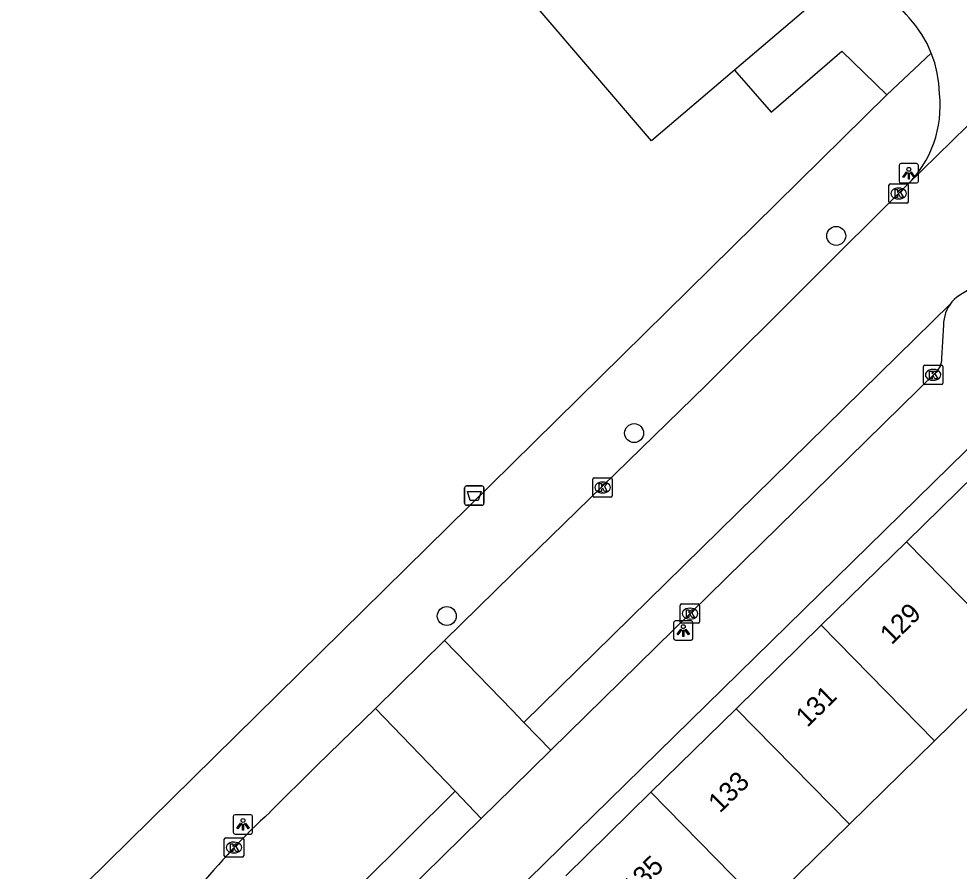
# Model space of a CAD drawing. Extents: x 159222 to 160346, y 381249 to 382166.
# Drawn here: x 159474.57 to 159523.05, y 381384.14 to 381428.08 of the extents above; entities that cross this region are included whole.
import ezdxf

# ---------------------------------------------------------------- set-up
doc = ezdxf.new("R2010")
doc.units = 0
for name, color, linetype in [('IMGEO_Afvalbak', 7, 'Continuous'), ('IMGEO_Boom', 7, 'Continuous'), ('IMGEO_Kolk', 7, 'Continuous'), ('IMGEO_Lichtpunt', 7, 'Continuous'), ('IMGEO_Pand', 7, 'Continuous'), ('IMGEO_Pand_nummerreeks', 7, 'Continuous'), ('IMGEO_Rijbaan_lokaal_gesloten', 7, 'Continuous'), ('IMGEO_Rijbaan_lokaal_open', 7, 'Continuous'), ('IMGEO_Voetpad_open', 7, 'Continuous')]:
    doc.layers.add(name, color=color, linetype=linetype)

msp = doc.modelspace()

# ---------------------------------------------------------------- linework, layer by layer
at = {"layer": 'IMGEO_Afvalbak'}
for p, q in [((159497.553, 381403.099), (159497.553, 381403.899)), ((159497.553, 381403.899), (159497.553, 381403.099)), ((159497.653, 381403.999), (159498.443, 381403.999)), ((159498.443, 381403.999), (159497.653, 381403.999)), ((159498.543, 381403.899), (159498.543, 381403.099)), ((159498.543, 381403.099), (159498.543, 381403.899)), ((159498.443, 381402.999), (159497.653, 381402.999)), ((159497.653, 381402.999), (159498.443, 381402.999))]:
    msp.add_line(p, q, dxfattribs=at)
msp.add_lwpolyline([(159497.696, 381403.713), (159498.4, 381403.713), (159498.251, 381403.243), (159497.845, 381403.243), (159497.696, 381403.713)], dxfattribs=at)
for centre, start, end in [((159497.653, 381403.899), 90, 180), ((159497.653, 381403.899), 90, 180), ((159498.443, 381403.899), 0, 90), ((159498.443, 381403.899), 360, 90), ((159497.653, 381403.099), 180, 270), ((159497.653, 381403.099), 180, 270), ((159498.443, 381403.099), 270, 0), ((159498.443, 381403.099), 270, 0)]:
    msp.add_arc(centre, 0.1, start, end, dxfattribs=at)
at = {"layer": 'IMGEO_Boom'}
for centre in [(159516.709, 381416.884), (159506.289, 381406.719), (159496.631, 381397.289)]:
    msp.add_circle(centre, 0.489, dxfattribs=at)
at = {"layer": 'IMGEO_Kolk'}
for p, q in [((159519.424, 381418.643), (159519.424, 381419.495)), ((159519.499, 381419.569), (159520.351, 381419.569)), ((159519.912, 381419.349), (159519.937, 381419.349)), ((159520.425, 381419.495), (159520.425, 381418.643)), ((159519.935, 381418.789), (159519.91, 381418.789)), ((159520.351, 381418.569), (159519.499, 381418.569)), ((159521.203, 381409.294), (159521.203, 381410.146)), ((159521.278, 381410.22), (159522.13, 381410.22)), ((159521.691, 381410), (159521.716, 381410)), ((159522.204, 381410.146), (159522.204, 381409.294)), ((159522.13, 381409.22), (159521.278, 381409.22)), ((159521.714, 381409.44), (159521.689, 381409.44)), ((159504.163, 381403.488), (159504.163, 381404.34)), ((159504.238, 381404.414), (159505.09, 381404.414)), ((159504.651, 381404.194), (159504.676, 381404.194)), ((159505.164, 381404.34), (159505.164, 381403.488)), ((159505.09, 381403.414), (159504.238, 381403.414)), ((159504.674, 381403.634), (159504.649, 381403.634)), ((159508.74, 381397.913), (159509.592, 381397.913)), ((159508.665, 381396.987), (159508.665, 381397.839)), ((159509.153, 381397.693), (159509.178, 381397.693)), ((159509.666, 381397.839), (159509.666, 381396.987)), ((159509.592, 381396.913), (159508.74, 381396.913)), ((159509.176, 381397.133), (159509.151, 381397.133)), ((159485.16, 381384.927), (159485.16, 381385.779)), ((159485.235, 381385.853), (159486.087, 381385.853)), ((159486.161, 381385.779), (159486.161, 381384.927)), ((159485.648, 381385.633), (159485.673, 381385.633)), ((159486.087, 381384.853), (159485.235, 381384.853)), ((159485.671, 381385.073), (159485.646, 381385.073))]:
    msp.add_line(p, q, dxfattribs=at)
for points in [[(159519.424, 381418.643), (159519.424, 381419.495)], [(159519.499, 381419.569), (159520.351, 381419.569)], [(159519.745, 381419.269), (159519.868, 381419.269), (159519.868, 381419.118), (159519.998, 381419.269), (159520.162, 381419.269), (159520.016, 381419.118), (159520.169, 381418.869), (159520.017, 381418.869), (159519.932, 381419.033), (159519.868, 381418.966), (159519.868, 381418.869), (159519.745, 381418.869), (159519.745, 381419.269)], [(159520.425, 381419.495), (159520.425, 381418.643)], [(159520.351, 381418.569), (159519.499, 381418.569)], [(159521.203, 381409.294), (159521.203, 381410.146)], [(159521.278, 381410.22), (159522.13, 381410.22)], [(159522.204, 381410.146), (159522.204, 381409.294)], [(159521.524, 381409.92), (159521.647, 381409.92), (159521.647, 381409.769), (159521.777, 381409.92), (159521.941, 381409.92), (159521.795, 381409.769), (159521.948, 381409.52), (159521.796, 381409.52), (159521.711, 381409.684), (159521.647, 381409.617), (159521.647, 381409.52), (159521.524, 381409.52), (159521.524, 381409.92)], [(159522.13, 381409.22), (159521.278, 381409.22)], [(159504.163, 381403.488), (159504.163, 381404.34)], [(159504.238, 381404.414), (159505.09, 381404.414)], [(159505.164, 381404.34), (159505.164, 381403.488)], [(159504.484, 381404.114), (159504.607, 381404.114), (159504.607, 381403.963), (159504.737, 381404.114), (159504.901, 381404.114), (159504.755, 381403.963), (159504.908, 381403.714), (159504.756, 381403.714), (159504.671, 381403.878), (159504.607, 381403.811), (159504.607, 381403.714), (159504.484, 381403.714), (159504.484, 381404.114)], [(159505.09, 381403.414), (159504.238, 381403.414)], [(159508.74, 381397.913), (159509.592, 381397.913)], [(159508.665, 381396.987), (159508.665, 381397.839)], [(159508.986, 381397.613), (159509.109, 381397.613), (159509.109, 381397.462), (159509.239, 381397.613), (159509.403, 381397.613), (159509.257, 381397.462), (159509.41, 381397.213), (159509.258, 381397.213), (159509.173, 381397.377), (159509.109, 381397.31), (159509.109, 381397.213), (159508.986, 381397.213), (159508.986, 381397.613)], [(159509.666, 381397.839), (159509.666, 381396.987)], [(159509.592, 381396.913), (159508.74, 381396.913)], [(159485.16, 381384.927), (159485.16, 381385.779)], [(159485.235, 381385.853), (159486.087, 381385.853)], [(159486.161, 381385.779), (159486.161, 381384.927)], [(159485.481, 381385.553), (159485.604, 381385.553), (159485.604, 381385.402), (159485.734, 381385.553), (159485.898, 381385.553), (159485.752, 381385.402), (159485.905, 381385.153), (159485.753, 381385.153), (159485.668, 381385.317), (159485.604, 381385.25), (159485.604, 381385.153), (159485.481, 381385.153), (159485.481, 381385.553)], [(159486.087, 381384.853), (159485.235, 381384.853)]]:
    msp.add_lwpolyline(points, dxfattribs=at)
for centre, start, end in [((159519.501, 381419.493), 91.552, 178.448), ((159519.501, 381419.493), 91.552, 178.448), ((159520.349, 381419.493), 1.552, 88.448), ((159520.349, 381419.493), 1.552, 88.448), ((159519.501, 381418.645), 181.552, 268.448), ((159519.501, 381418.645), 181.552, 268.448), ((159520.349, 381418.645), 271.552, 358.448), ((159520.349, 381418.645), 271.552, 358.448), ((159521.28, 381410.144), 91.552, 178.448), ((159521.28, 381410.144), 91.552, 178.448), ((159522.128, 381410.144), 1.552, 88.448), ((159522.128, 381410.144), 1.552, 88.448), ((159521.28, 381409.296), 181.552, 268.448), ((159521.28, 381409.296), 181.552, 268.448), ((159522.128, 381409.296), 271.552, 358.448), ((159522.128, 381409.296), 271.552, 358.448), ((159504.24, 381404.338), 91.552, 178.448), ((159504.24, 381404.338), 91.552, 178.448), ((159505.088, 381404.338), 1.552, 88.448), ((159505.088, 381404.338), 1.552, 88.448), ((159504.24, 381403.49), 181.552, 268.448), ((159504.24, 381403.49), 181.552, 268.448), ((159505.088, 381403.49), 271.552, 358.448), ((159505.088, 381403.49), 271.552, 358.448), ((159508.742, 381397.837), 91.552, 178.448), ((159508.742, 381397.837), 91.552, 178.448), ((159509.59, 381397.837), 1.552, 88.448), ((159509.59, 381397.837), 1.552, 88.448), ((159508.742, 381396.989), 181.552, 268.448), ((159508.742, 381396.989), 181.552, 268.448), ((159509.59, 381396.989), 271.552, 358.448), ((159509.59, 381396.989), 271.552, 358.448), ((159485.237, 381385.777), 91.552, 178.448), ((159485.237, 381385.777), 91.552, 178.448), ((159486.085, 381385.777), 1.552, 88.448), ((159486.085, 381385.777), 1.552, 88.448), ((159485.237, 381384.929), 181.552, 268.448), ((159485.237, 381384.929), 181.552, 268.448), ((159486.085, 381384.929), 271.552, 358.448), ((159486.085, 381384.929), 271.552, 358.448)]:
    msp.add_arc(centre, 0.0765, start, end, dxfattribs=at)
for centre, major_axis, ratio, start_param, end_param in [((159519.911, 381419.069), (-0.387, 0.002), 0.722429, 4.712389, 7.853982), ((159519.936, 381419.069), (-0.39, 0.002), 0.717154, 1.570796, 4.712389), ((159521.69, 381409.72), (-0.387, 0.002), 0.722429, 4.712389, 7.853982), ((159521.715, 381409.72), (-0.39, 0.002), 0.717154, 1.570796, 4.712389), ((159504.65, 381403.914), (-0.387, 0.002), 0.722429, 4.712389, 7.853982), ((159504.675, 381403.914), (-0.39, 0.002), 0.717154, 1.570796, 4.712389), ((159509.152, 381397.413), (-0.387, 0.002), 0.722429, 4.712389, 7.853982), ((159509.177, 381397.413), (-0.39, 0.002), 0.717154, 1.570796, 4.712389), ((159485.647, 381385.353), (-0.387, 0.002), 0.722429, 4.712389, 7.853982), ((159485.672, 381385.353), (-0.39, 0.002), 0.717154, 1.570796, 4.712389)]:
    msp.add_ellipse(centre, major_axis=major_axis, ratio=ratio, start_param=start_param, end_param=end_param, dxfattribs=at)
at = {"layer": 'IMGEO_Lichtpunt'}
for p, q in [((159519.951, 381420.517), (159519.951, 381419.71)), ((159519.951, 381420.517), (159519.951, 381419.71)), ((159520.853, 381420.612), (159520.045, 381420.612)), ((159520.853, 381420.612), (159520.045, 381420.612)), ((159520.947, 381419.71), (159520.947, 381420.517)), ((159520.947, 381419.71), (159520.947, 381420.517)), ((159520.045, 381419.616), (159520.853, 381419.616)), ((159520.045, 381419.616), (159520.853, 381419.616)), ((159508.325, 381396.945), (159508.325, 381396.138)), ((159508.325, 381396.945), (159508.325, 381396.138)), ((159509.227, 381397.04), (159508.419, 381397.04)), ((159509.227, 381397.04), (159508.419, 381397.04)), ((159509.321, 381396.138), (159509.321, 381396.945)), ((159509.321, 381396.138), (159509.321, 381396.945)), ((159508.419, 381396.044), (159509.227, 381396.044)), ((159508.419, 381396.044), (159509.227, 381396.044)), ((159485.628, 381386.95), (159485.628, 381386.143)), ((159485.628, 381386.95), (159485.628, 381386.143)), ((159486.53, 381387.045), (159485.722, 381387.045)), ((159486.53, 381387.045), (159485.722, 381387.045)), ((159486.624, 381386.143), (159486.624, 381386.95)), ((159486.624, 381386.143), (159486.624, 381386.95)), ((159485.722, 381386.049), (159486.53, 381386.049)), ((159485.722, 381386.049), (159486.53, 381386.049))]:
    msp.add_line(p, q, dxfattribs=at)
for points in [[(159520.325, 381420.181), (159520.364, 381420.153), (159520.176, 381419.891), (159520.138, 381419.918), (159520.325, 381420.181)], [(159520.537, 381420.153), (159520.575, 381420.18), (159520.762, 381419.918), (159520.723, 381419.89), (159520.537, 381420.153)], [(159520.427, 381420.133), (159520.474, 381420.133), (159520.474, 381419.811), (159520.427, 381419.811), (159520.427, 381420.133)], [(159508.699, 381396.609), (159508.738, 381396.581), (159508.55, 381396.319), (159508.512, 381396.346), (159508.699, 381396.609)], [(159508.801, 381396.561), (159508.848, 381396.561), (159508.848, 381396.239), (159508.801, 381396.239), (159508.801, 381396.561)], [(159508.911, 381396.581), (159508.949, 381396.608), (159509.136, 381396.346), (159509.097, 381396.318), (159508.911, 381396.581)], [(159486.002, 381386.614), (159486.041, 381386.586), (159485.853, 381386.324), (159485.815, 381386.351), (159486.002, 381386.614)], [(159486.104, 381386.566), (159486.151, 381386.566), (159486.151, 381386.244), (159486.104, 381386.244), (159486.104, 381386.566)], [(159486.214, 381386.586), (159486.252, 381386.613), (159486.439, 381386.351), (159486.4, 381386.323), (159486.214, 381386.586)]]:
    msp.add_lwpolyline(points, dxfattribs=at)
for centre in [(159520.45, 381420.315), (159508.824, 381396.743), (159486.127, 381386.748)]:
    msp.add_circle(centre, 0.0994, dxfattribs=at)
for centre, start, end in [((159520.045, 381420.517), 90, 180), ((159520.045, 381420.517), 90, 180), ((159520.853, 381420.517), 0, 90), ((159520.853, 381420.517), 0, 90), ((159520.045, 381419.71), 180, 270), ((159520.045, 381419.71), 180, 270), ((159520.853, 381419.71), 270, 0), ((159520.853, 381419.71), 270, 360), ((159508.419, 381396.945), 90, 180), ((159508.419, 381396.945), 90, 180), ((159509.227, 381396.945), 0, 90), ((159509.227, 381396.945), 0, 90), ((159508.419, 381396.138), 180, 270), ((159508.419, 381396.138), 180, 270), ((159509.227, 381396.138), 270, 0), ((159509.227, 381396.138), 270, 360), ((159485.722, 381386.95), 90, 180), ((159485.722, 381386.95), 90, 180), ((159486.53, 381386.95), 0, 90), ((159486.53, 381386.95), 0, 90), ((159485.722, 381386.143), 180, 270), ((159485.722, 381386.143), 180, 270), ((159486.53, 381386.143), 270, 0), ((159486.53, 381386.143), 270, 360)]:
    msp.add_arc(centre, 0.0946, start, end, dxfattribs=at)
at = {"layer": 'IMGEO_Pand'}
for points in [[(159509.387, 381435.727), (159515.357, 381428.751), (159511.463, 381425.436)], [(159511.463, 381425.436), (159507.177, 381421.789), (159501.232, 381428.731)], [(159524.724, 381405.421), (159520.331, 381401.117)], [(159520.331, 381401.117), (159515.938, 381396.813)], [(159525.882, 381395.453), (159520.331, 381401.117)], [(159515.938, 381396.813), (159511.546, 381392.509)], [(159515.938, 381396.813), (159521.776, 381390.857)], [(159521.776, 381390.857), (159526.123, 381395.12), (159525.882, 381395.453)], [(159511.546, 381392.509), (159507.153, 381388.204)], [(159517.385, 381386.551), (159511.546, 381392.509)], [(159517.385, 381386.551), (159521.776, 381390.857)], [(159502.761, 381383.899), (159507.153, 381388.204)], [(159507.153, 381388.204), (159512.994, 381382.244)], [(159512.994, 381382.244), (159517.385, 381386.551)]]:
    msp.add_lwpolyline(points, dxfattribs=at)
at = {"layer": 'IMGEO_Rijbaan_lokaal_gesloten'}
for points in [[(159533.511, 381432.388), (159520.372, 381419.512)], [(159496.517, 381396.025), (159500, 381399.447), (159509.99, 381409.17), (159520.372, 381419.512)], [(159527.135, 381414.989), (159526.531, 381414.985), (159525.93, 381414.928), (159525.336, 381414.817), (159524.755, 381414.653), (159524.19, 381414.439), (159523.647, 381414.174), (159523.13, 381413.862), (159522.909, 381413.709), (159522.787, 381413.6), (159522.676, 381413.48), (159522.6, 381413.383)], [(159500.611, 381391.798), (159522.6, 381413.383)], [(159487.518, 381387.178), (159489.934, 381389.578), (159492.951, 381392.52)], [(159497.057, 381388.261), (159489.732, 381380.972), (159488.003, 381378.683)]]:
    msp.add_lwpolyline(points, dxfattribs=at)
msp.add_arc((159511.102, 381361.325), 34.993, 132.372, 141.4169, dxfattribs=at)
at = {"layer": 'IMGEO_Rijbaan_lokaal_open'}
for points in [[(159521.61, 381426.308), (159521.388, 381426.8), (159521.124, 381427.27), (159520.819, 381427.715), (159520.475, 381428.131), (159520.317, 381428.299), (159500, 381452.168), (159499.131, 381453.073), (159498.86, 381453.295), (159498.571, 381453.491), (159498.265, 381453.661), (159497.946, 381453.803), (159497.726, 381453.882), (159496.408, 381454.265), (159496.02, 381454.339), (159495.627, 381454.379), (159495.232, 381454.383), (159494.838, 381454.352), (159494.448, 381454.285), (159494.066, 381454.185), (159493.695, 381454.05), (159493.336, 381453.883), (159492.995, 381453.684), (159492.918, 381453.634)], [(159522.034, 381424.203), (159521.999, 381424.741), (159521.916, 381425.274), (159521.786, 381425.798), (159521.61, 381426.308)], [(159492.951, 381392.52), (159496.517, 381396.025)], [(159496.517, 381396.025), (159500, 381392.429), (159500.611, 381391.798)], [(159497.057, 381388.261), (159492.951, 381392.52)], [(159500.611, 381391.798), (159501.993, 381390.372)], [(159501.993, 381390.372), (159500, 381388.415), (159498.411, 381386.856)], [(159498.411, 381386.856), (159497.057, 381388.261)]]:
    msp.add_lwpolyline(points, dxfattribs=at)
msp.add_arc((159516.338, 381423.581), 5.73, 314.7522, 6.2298, dxfattribs=at)
at = {"layer": 'IMGEO_Voetpad_open'}
for points in [[(159511.463, 381425.436), (159513.358, 381423.27), (159516.999, 381426.4), (159519.316, 381424.154)], [(159519.316, 381424.154), (159521.61, 381426.308)], [(159519.316, 381424.154), (159500, 381405.14), (159472.543, 381378.114)], [(159522.6, 381413.383), (159522.575, 381413.351), (159522.487, 381413.213), (159522.411, 381413.068), (159522.348, 381412.917), (159522.3, 381412.761), (159522.265, 381412.601), (159522.245, 381412.439), (159522.239, 381412.305), (159522.143, 381410.574), (159522.142, 381410.537), (159522.133, 381410.444), (159522.116, 381410.353), (159522.091, 381410.263), (159522.058, 381410.175), (159522.017, 381410.091), (159521.969, 381410.011), (159521.914, 381409.936), (159521.852, 381409.866), (159501.993, 381390.372)], [(159492.843, 381375.889), (159500, 381382.896), (159528.398, 381410.697)], [(159498.411, 381386.856), (159494.435, 381382.959), (159491.114, 381379.546), (159489.385, 381377.257), (159488.139, 381374.839), (159487.224, 381372.977), (159486.118, 381370.557), (159485.124, 381368.137), (159484.233, 381365.792), (159482.589, 381361.013)]]:
    msp.add_lwpolyline(points, dxfattribs=at)

# ---------------------------------------------------------------- texts
at = {"layer": 'IMGEO_Pand_nummerreeks'}
for s, p in [('129', (159519.563, 381395.772)), ('131', (159515.218, 381391.514)), ('133', (159510.711, 381387.098)), ('135', (159506.284, 381382.76))]:
    msp.add_text(s, height=1, rotation=44.419, dxfattribs=at).set_placement(p)

doc.saveas('drawing.dxf')
